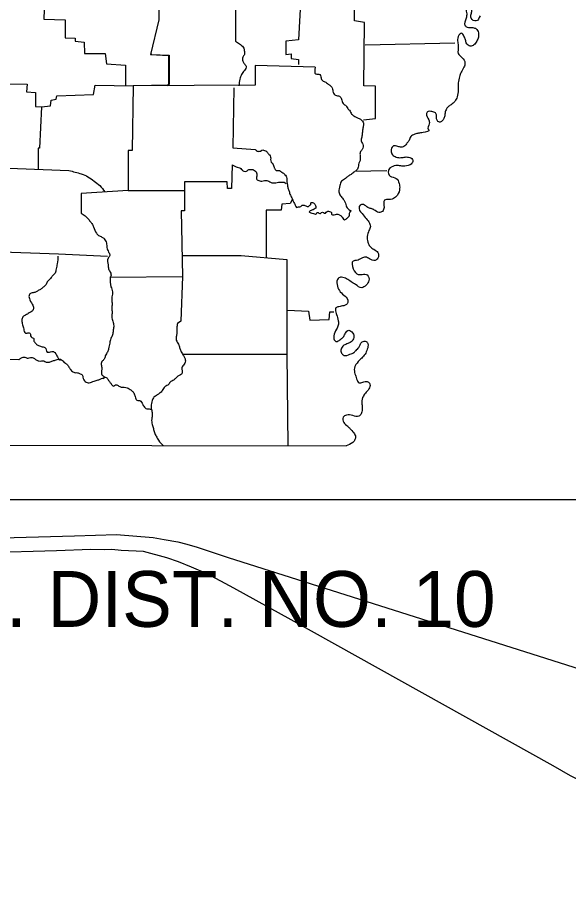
# Model space of a CAD drawing. Extents: x 1671357 to 13005564, y 567358 to 14261451.
# Drawn here: x 12758336.04 to 12758345.91, y 14259847.06 to 14259862.6 of the extents above; entities that cross this region are included whole.
import ezdxf

# ---------------------------------------------------------------- set-up
doc = ezdxf.new("R2010")
doc.units = 0
for name, color, linetype in [('1', 7, 'Continuous'), ('2', 7, 'Continuous'), ('40', 7, 'Continuous'), ('60', 7, 'Continuous')]:
    doc.layers.add(name, color=color, linetype=linetype)

msp = doc.modelspace()

# ---------------------------------------------------------------- linework, layer by layer
at = {"layer": '1'}
msp.add_line((12758342.084, 14259859.844), (12758342.654, 14259859.854), dxfattribs=at)
for points in [[(12758339.534, 14259863.784), (12758339.534, 14259863.274), (12758339.944, 14259863.264), (12758339.944, 14259862.174)], [(12758338.404, 14259863.654), (12758338.574, 14259863.644), (12758338.574, 14259862.554), (12758338.424, 14259861.934), (12758338.744, 14259861.914), (12758338.744, 14259861.394)], [(12758342.234, 14259860.764), (12758342.454, 14259860.784), (12758342.454, 14259861.364), (12758342.244, 14259861.374), (12758342.254, 14259862.504), (12758342.074, 14259862.534), (12758342.074, 14259863.294), (12758344.504, 14259863.314)], [(12758336.203, 14259862.934), (12758336.523, 14259862.914), (12758336.513, 14259862.564), (12758336.893, 14259862.554), (12758336.893, 14259862.234), (12758337.073, 14259862.224), (12758337.073, 14259862.174), (12758337.233, 14259862.154), (12758337.243, 14259861.954), (12758337.613, 14259861.954), (12758337.633, 14259861.764), (12758337.973, 14259861.744), (12758337.973, 14259861.374)], [(12758341.114, 14259862.974), (12758341.074, 14259862.194), (12758340.844, 14259862.174), (12758340.844, 14259861.934), (12758340.944, 14259861.944), (12758340.944, 14259861.864), (12758341.074, 14259861.844), (12758341.074, 14259861.754)], [(12758342.264, 14259862.104), (12758343.874, 14259862.144)], [(12758338.434, 14259861.944), (12758338.434, 14259861.934), (12758338.754, 14259861.924), (12758338.754, 14259861.394)], [(12758341.374, 14259861.704), (12758340.294, 14259861.734), (12758340.294, 14259861.384), (12758338.113, 14259861.374), (12758338.093, 14259860.214), (12758338.023, 14259860.214), (12758338.023, 14259859.494), (12758337.183, 14259859.444), (12758337.183, 14259859.093)], [(12758333.803, 14259860.934), (12758335.433, 14259860.914), (12758335.463, 14259861.184), (12758335.593, 14259861.184), (12758335.593, 14259861.414), (12758336.213, 14259861.404), (12758336.203, 14259861.264), (12758336.363, 14259861.254), (12758336.363, 14259861.004), (12758336.473, 14259860.994), (12758336.433, 14259860.254), (12758336.413, 14259860.254), (12758336.413, 14259859.874)], [(12758336.473, 14259860.994), (12758336.633, 14259861.014), (12758336.643, 14259861.114), (12758336.733, 14259861.134), (12758336.743, 14259861.194), (12758337.403, 14259861.214), (12758337.433, 14259861.384), (12758338.113, 14259861.374)], [(12758338.754, 14259861.384), (12758338.123, 14259861.374)], [(12758338.714, 14259861.374), (12758338.754, 14259861.414)], [(12758339.914, 14259861.334), (12758339.894, 14259860.264), (12758340.294, 14259860.234)], [(12758333.473, 14259860.174), (12758333.463, 14259860.334), (12758333.513, 14259860.334), (12758333.533, 14259860.704), (12758333.973, 14259860.674), (12758333.963, 14259860.454), (12758334.533, 14259860.414), (12758334.533, 14259860.284), (12758335.053, 14259860.254), (12758335.133, 14259860.094), (12758335.083, 14259860.024), (12758335.113, 14259859.924), (12758336.963, 14259859.854)], [(12758339.884, 14259859.954), (12758339.874, 14259859.534), (12758339.804, 14259859.534), (12758339.794, 14259859.654), (12758339.034, 14259859.654), (12758339.034, 14259859.133), (12758338.974, 14259859.133), (12758338.994, 14259857.953)], [(12758338.023, 14259859.494), (12758339.024, 14259859.494)], [(12758340.964, 14259859.344), (12758340.924, 14259859.263), (12758340.774, 14259859.253), (12758340.764, 14259859.143), (12758340.494, 14259859.143), (12758340.494, 14259858.293)], [(12758335.593, 14259858.403), (12758336.773, 14259858.363), (12758337.653, 14259858.323)], [(12758338.984, 14259858.333), (12758340.044, 14259858.333), (12758340.864, 14259858.263)], [(12758340.864, 14259858.263), (12758340.864, 14259856.563), (12758340.884, 14259854.923)], [(12758337.703, 14259857.943), (12758338.994, 14259857.953), (12758338.964, 14259857.153), (12758338.904, 14259857.113)], [(12758340.874, 14259857.353), (12758341.254, 14259857.333), (12758341.274, 14259857.173), (12758341.624, 14259857.183), (12758341.634, 14259857.323), (12758341.704, 14259857.323)], [(12758331.473, 14259857.243), (12758331.483, 14259854.943), (12758341.924, 14259854.923)], [(12758336.063, 14259856.463), (12758334.843, 14259856.503), (12758334.843, 14259856.793)], [(12758339.014, 14259856.563), (12758340.864, 14259856.563)]]:
    msp.add_lwpolyline(points, dxfattribs=at)
for points in [[(12758344.324, 14259862.624), (12758344.254, 14259862.534), (12758344.164, 14259862.584), (12758344.164, 14259862.654), (12758344.174, 14259862.724), (12758344.144, 14259862.774), (12758344.084, 14259862.754), (12758344.084, 14259862.664), (12758344.074, 14259862.584), (12758344.054, 14259862.454), (12758344.094, 14259862.424), (12758344.194, 14259862.414), (12758344.254, 14259862.394), (12758344.294, 14259862.324), (12758344.294, 14259862.244), (12758344.264, 14259862.174), (12758344.214, 14259862.104), (12758344.144, 14259862.084), (12758344.084, 14259862.124), (12758344.064, 14259862.194), (12758344.034, 14259862.264), (12758343.994, 14259862.314), (12758343.934, 14259862.254), (12758343.924, 14259862.154), (12758343.934, 14259862.074), (12758343.934, 14259861.954), (12758344.004, 14259861.874), (12758344.054, 14259861.784), (12758344.034, 14259861.704), (12758343.984, 14259861.614), (12758343.954, 14259861.534), (12758343.934, 14259861.424), (12758343.934, 14259861.294), (12758343.914, 14259861.174), (12758343.874, 14259861.094), (12758343.804, 14259861.034), (12758343.754, 14259860.994), (12758343.714, 14259860.944), (12758343.694, 14259860.864), (12758343.684, 14259860.804), (12758343.634, 14259860.734), (12758343.584, 14259860.724), (12758343.554, 14259860.754), (12758343.544, 14259860.804), (12758343.544, 14259860.854), (12758343.514, 14259860.894), (12758343.444, 14259860.914), (12758343.394, 14259860.914), (12758343.364, 14259860.874), (12758343.404, 14259860.764), (12758343.414, 14259860.694), (12758343.394, 14259860.594), (12758343.404, 14259860.584), (12758343.304, 14259860.534), (12758343.224, 14259860.524), (12758343.154, 14259860.504), (12758343.084, 14259860.464), (12758343.054, 14259860.394), (12758343.014, 14259860.344), (12758342.974, 14259860.294), (12758342.914, 14259860.274), (12758342.854, 14259860.284), (12758342.774, 14259860.294), (12758342.734, 14259860.234), (12758342.744, 14259860.154), (12758342.804, 14259860.104), (12758342.884, 14259860.084), (12758342.964, 14259860.094), (12758343.044, 14259860.094), (12758343.114, 14259860.054), (12758343.104, 14259859.984), (12758343.034, 14259859.944), (12758342.924, 14259859.934), (12758342.844, 14259859.944), (12758342.734, 14259859.914), (12758342.684, 14259859.854), (12758342.714, 14259859.754), (12758342.824, 14259859.714), (12758342.874, 14259859.624), (12758342.884, 14259859.534), (12758342.844, 14259859.414), (12758342.794, 14259859.364), (12758342.694, 14259859.334), (12758342.614, 14259859.323), (12758342.604, 14259859.193), (12758342.574, 14259859.123), (12758342.514, 14259859.103), (12758342.424, 14259859.153), (12758342.374, 14259859.173), (12758342.314, 14259859.193), (12758342.234, 14259859.243), (12758342.174, 14259859.233), (12758342.184, 14259859.113), (12758342.194, 14259859.103), (12758342.264, 14259859.013), (12758342.334, 14259858.933), (12758342.364, 14259858.853)], [(12758339.944, 14259862.174), (12758340.014, 14259862.124), (12758340.084, 14259862.064), (12758340.104, 14259861.984), (12758340.104, 14259861.934), (12758340.074, 14259861.884), (12758340.074, 14259861.814), (12758340.104, 14259861.764), (12758340.134, 14259861.724), (12758340.104, 14259861.644), (12758340.054, 14259861.574), (12758340.024, 14259861.494), (12758340.004, 14259861.374)], [(12758341.374, 14259861.704), (12758341.384, 14259861.584), (12758341.454, 14259861.574), (12758341.474, 14259861.534), (12758341.494, 14259861.474), (12758341.544, 14259861.444), (12758341.604, 14259861.404), (12758341.644, 14259861.374), (12758341.674, 14259861.334), (12758341.694, 14259861.254), (12758341.734, 14259861.204), (12758341.804, 14259861.184), (12758341.844, 14259861.134), (12758341.874, 14259861.054), (12758341.924, 14259861.014), (12758341.964, 14259860.954), (12758341.984, 14259860.934), (12758342.024, 14259860.864), (12758342.064, 14259860.834), (12758342.094, 14259860.814), (12758342.144, 14259860.794), (12758342.194, 14259860.764), (12758342.234, 14259860.704), (12758342.234, 14259860.664), (12758342.224, 14259860.594), (12758342.214, 14259860.524), (12758342.204, 14259860.454), (12758342.194, 14259860.384), (12758342.224, 14259860.324), (12758342.214, 14259860.234), (12758342.184, 14259860.194), (12758342.174, 14259860.134), (12758342.174, 14259860.034), (12758342.154, 14259859.984), (12758342.134, 14259859.894), (12758342.094, 14259859.844)], [(12758340.294, 14259860.234), (12758340.334, 14259860.204), (12758340.394, 14259860.204), (12758340.434, 14259860.224), (12758340.464, 14259860.214), (12758340.504, 14259860.194), (12758340.534, 14259860.154), (12758340.554, 14259860.134), (12758340.574, 14259860.094), (12758340.574, 14259860.054), (12758340.584, 14259860.004), (12758340.604, 14259859.984), (12758340.624, 14259859.944), (12758340.634, 14259859.914), (12758340.644, 14259859.894), (12758340.674, 14259859.854), (12758340.704, 14259859.854), (12758340.734, 14259859.854), (12758340.764, 14259859.834), (12758340.814, 14259859.794), (12758340.824, 14259859.784), (12758340.864, 14259859.714), (12758340.864, 14259859.664), (12758340.874, 14259859.604), (12758340.884, 14259859.544), (12758340.904, 14259859.484), (12758340.914, 14259859.444), (12758340.944, 14259859.384), (12758340.964, 14259859.344), (12758340.984, 14259859.293), (12758341.014, 14259859.233), (12758341.034, 14259859.193), (12758341.074, 14259859.203), (12758341.114, 14259859.213), (12758341.134, 14259859.233), (12758341.174, 14259859.233), (12758341.204, 14259859.223), (12758341.254, 14259859.213), (12758341.274, 14259859.233), (12758341.294, 14259859.243), (12758341.294, 14259859.273), (12758341.324, 14259859.283), (12758341.354, 14259859.263), (12758341.384, 14259859.213), (12758341.384, 14259859.193), (12758341.374, 14259859.173), (12758341.334, 14259859.153), (12758341.284, 14259859.133), (12758341.264, 14259859.113), (12758341.314, 14259859.093), (12758341.394, 14259859.083), (12758341.414, 14259859.103), (12758341.464, 14259859.083), (12758341.484, 14259859.103), (12758341.554, 14259859.093), (12758341.584, 14259859.123), (12758341.644, 14259859.113), (12758341.664, 14259859.103), (12758341.664, 14259859.073), (12758341.714, 14259859.063), (12758341.754, 14259859.073), (12758341.804, 14259859.063), (12758341.844, 14259859.033), (12758341.864, 14259859.003), (12758341.894, 14259858.973), (12758341.924, 14259858.983), (12758341.944, 14259859.003), (12758341.984, 14259859.053), (12758341.984, 14259859.083), (12758341.994, 14259859.103), (12758342.014, 14259859.133)], [(12758339.884, 14259859.954), (12758339.934, 14259859.934), (12758339.974, 14259859.914), (12758340.024, 14259859.904), (12758340.054, 14259859.874), (12758340.094, 14259859.844), (12758340.144, 14259859.844), (12758340.184, 14259859.874), (12758340.224, 14259859.874), (12758340.254, 14259859.874), (12758340.284, 14259859.854), (12758340.314, 14259859.834), (12758340.324, 14259859.794), (12758340.324, 14259859.754), (12758340.324, 14259859.694), (12758340.344, 14259859.684), (12758340.414, 14259859.664), (12758340.464, 14259859.674), (12758340.504, 14259859.674), (12758340.544, 14259859.664), (12758340.574, 14259859.644), (12758340.594, 14259859.634), (12758340.634, 14259859.634), (12758340.664, 14259859.634), (12758340.714, 14259859.644), (12758340.734, 14259859.644), (12758340.784, 14259859.644), (12758340.814, 14259859.644), (12758340.854, 14259859.624)], [(12758336.963, 14259859.854), (12758337.183, 14259859.794), (12758337.303, 14259859.744), (12758337.413, 14259859.664), (12758337.513, 14259859.584), (12758337.603, 14259859.474)], [(12758342.074, 14259859.834), (12758342.014, 14259859.784), (12758341.964, 14259859.754), (12758341.914, 14259859.714), (12758341.844, 14259859.664), (12758341.814, 14259859.584), (12758341.794, 14259859.474), (12758341.824, 14259859.404), (12758341.874, 14259859.344), (12758341.904, 14259859.293), (12758341.934, 14259859.203), (12758341.994, 14259859.143), (12758342.014, 14259859.133)], [(12758337.183, 14259859.093), (12758337.253, 14259859.043), (12758337.303, 14259858.993), (12758337.343, 14259858.943), (12758337.373, 14259858.903), (12758337.403, 14259858.843), (12758337.453, 14259858.733), (12758337.493, 14259858.693), (12758337.553, 14259858.663), (12758337.593, 14259858.633), (12758337.633, 14259858.553), (12758337.643, 14259858.473), (12758337.673, 14259858.393), (12758337.693, 14259858.333), (12758337.663, 14259858.283), (12758337.663, 14259858.163), (12758337.673, 14259858.093), (12758337.703, 14259858.033), (12758337.713, 14259857.963), (12758337.703, 14259857.943)], [(12758342.364, 14259858.853), (12758342.334, 14259858.783), (12758342.304, 14259858.673), (12758342.314, 14259858.573), (12758342.354, 14259858.493), (12758342.424, 14259858.443), (12758342.494, 14259858.383), (12758342.494, 14259858.283), (12758342.444, 14259858.243), (12758342.344, 14259858.273), (12758342.274, 14259858.303), (12758342.204, 14259858.283), (12758342.114, 14259858.243), (12758342.054, 14259858.233), (12758342.054, 14259858.093), (12758342.144, 14259857.993), (12758342.214, 14259857.993), (12758342.304, 14259857.983), (12758342.334, 14259857.883), (12758342.284, 14259857.803), (12758342.204, 14259857.753), (12758342.094, 14259857.813), (12758342.014, 14259857.863), (12758341.934, 14259857.913), (12758341.844, 14259857.943), (12758341.784, 14259857.923), (12758341.764, 14259857.813), (12758341.804, 14259857.703), (12758341.884, 14259857.623), (12758341.954, 14259857.533), (12758341.934, 14259857.453), (12758341.884, 14259857.433), (12758341.794, 14259857.413), (12758341.744, 14259857.393), (12758341.734, 14259857.363), (12758341.754, 14259857.273), (12758341.784, 14259857.163), (12758341.784, 14259857.083), (12758341.754, 14259857.013), (12758341.704, 14259856.893), (12758341.714, 14259856.823), (12758341.744, 14259856.793), (12758341.784, 14259856.803), (12758341.844, 14259856.843), (12758341.884, 14259856.883), (12758341.914, 14259856.943), (12758341.974, 14259856.993), (12758342.044, 14259856.943), (12758342.064, 14259856.863), (12758342.014, 14259856.783), (12758341.954, 14259856.753), (12758341.884, 14259856.723), (12758341.834, 14259856.653), (12758341.844, 14259856.583), (12758341.884, 14259856.543), (12758341.994, 14259856.563), (12758342.064, 14259856.593), (12758342.104, 14259856.633), (12758342.154, 14259856.683), (12758342.174, 14259856.733), (12758342.214, 14259856.783), (12758342.284, 14259856.793), (12758342.314, 14259856.753), (12758342.304, 14259856.653), (12758342.264, 14259856.563), (12758342.204, 14259856.493), (12758342.144, 14259856.433), (12758342.074, 14259856.313), (12758342.084, 14259856.213), (12758342.114, 14259856.123), (12758342.154, 14259856.053), (12758342.224, 14259856.063), (12758342.304, 14259856.073), (12758342.344, 14259856.043), (12758342.344, 14259855.963), (12758342.284, 14259855.883), (12758342.234, 14259855.813), (12758342.204, 14259855.703), (12758342.214, 14259855.633), (12758342.214, 14259855.573), (12758342.194, 14259855.493), (12758342.154, 14259855.453), (12758342.044, 14259855.463), (12758341.934, 14259855.473), (12758341.874, 14259855.433), (12758341.884, 14259855.343), (12758341.954, 14259855.273), (12758341.994, 14259855.233), (12758342.064, 14259855.153), (12758342.094, 14259855.083), (12758342.084, 14259855.033), (12758342.044, 14259854.983), (12758341.924, 14259854.923)], [(12758336.763, 14259858.323), (12758336.753, 14259858.183), (12758336.733, 14259858.093), (12758336.713, 14259858.013), (12758336.673, 14259857.973), (12758336.633, 14259857.923), (12758336.583, 14259857.873), (12758336.553, 14259857.813), (12758336.513, 14259857.773), (12758336.463, 14259857.733), (12758336.413, 14259857.703), (12758336.363, 14259857.673), (12758336.303, 14259857.663), (12758336.253, 14259857.633), (12758336.253, 14259857.563), (12758336.303, 14259857.463), (12758336.323, 14259857.423), (12758336.323, 14259857.363), (12758336.303, 14259857.333), (12758336.263, 14259857.313), (12758336.203, 14259857.273), (12758336.163, 14259857.253), (12758336.123, 14259857.203), (12758336.123, 14259857.133), (12758336.143, 14259857.053), (12758336.153, 14259857.013), (12758336.183, 14259856.943), (12758336.213, 14259856.943), (12758336.263, 14259856.943), (12758336.273, 14259856.923), (12758336.273, 14259856.913), (12758336.283, 14259856.873), (12758336.333, 14259856.843), (12758336.333, 14259856.813), (12758336.363, 14259856.763), (12758336.403, 14259856.723), (12758336.433, 14259856.713), (12758336.503, 14259856.693), (12758336.533, 14259856.683), (12758336.573, 14259856.603), (12758336.613, 14259856.603), (12758336.653, 14259856.613), (12758336.713, 14259856.593), (12758336.733, 14259856.563), (12758336.763, 14259856.503), (12758336.793, 14259856.463), (12758336.813, 14259856.463)], [(12758337.703, 14259857.943), (12758337.713, 14259857.773), (12758337.743, 14259857.683), (12758337.733, 14259857.593), (12758337.733, 14259857.503), (12758337.733, 14259857.423), (12758337.733, 14259857.353), (12758337.733, 14259857.273), (12758337.733, 14259857.213), (12758337.753, 14259857.133), (12758337.763, 14259857.053), (12758337.753, 14259856.983), (12758337.743, 14259856.913), (12758337.713, 14259856.843), (12758337.693, 14259856.763), (12758337.673, 14259856.663), (12758337.653, 14259856.603), (12758337.613, 14259856.533), (12758337.593, 14259856.473), (12758337.553, 14259856.433), (12758337.543, 14259856.363), (12758337.553, 14259856.293), (12758337.543, 14259856.243), (12758337.563, 14259856.183), (12758337.613, 14259856.153)], [(12758338.904, 14259857.113), (12758338.894, 14259857.033), (12758338.894, 14259856.943), (12758338.884, 14259856.873), (12758338.884, 14259856.813), (12758338.924, 14259856.743), (12758338.944, 14259856.683), (12758338.964, 14259856.623), (12758339.004, 14259856.553), (12758339.034, 14259856.503), (12758339.044, 14259856.423), (12758339.024, 14259856.383), (12758338.984, 14259856.323), (12758338.984, 14259856.213), (12758338.934, 14259856.183), (12758338.864, 14259856.123), (12758338.824, 14259856.093), (12758338.784, 14259856.073), (12758338.744, 14259856.023), (12758338.684, 14259855.983), (12758338.634, 14259855.913), (12758338.584, 14259855.863), (12758338.544, 14259855.833), (12758338.484, 14259855.793), (12758338.454, 14259855.733), (12758338.434, 14259855.633), (12758338.444, 14259855.553), (12758338.454, 14259855.483), (12758338.444, 14259855.403), (12758338.454, 14259855.303), (12758338.474, 14259855.233), (12758338.494, 14259855.163), (12758338.524, 14259855.093), (12758338.564, 14259855.023), (12758338.654, 14259854.923)], [(12758336.063, 14259856.463), (12758336.103, 14259856.493), (12758336.153, 14259856.513), (12758336.193, 14259856.503), (12758336.233, 14259856.493), (12758336.273, 14259856.503), (12758336.333, 14259856.493), (12758336.373, 14259856.463), (12758336.423, 14259856.443), (12758336.473, 14259856.443), (12758336.513, 14259856.443), (12758336.553, 14259856.423), (12758336.613, 14259856.423), (12758336.673, 14259856.443), (12758336.733, 14259856.463), (12758336.813, 14259856.473), (12758336.873, 14259856.423), (12758336.923, 14259856.383), (12758336.963, 14259856.333), (12758336.993, 14259856.283), (12758337.023, 14259856.253), (12758337.073, 14259856.233), (12758337.113, 14259856.233), (12758337.163, 14259856.213), (12758337.193, 14259856.203), (12758337.213, 14259856.153), (12758337.253, 14259856.073), (12758337.323, 14259856.053), (12758337.413, 14259856.083), (12758337.483, 14259856.103), (12758337.533, 14259856.123), (12758337.563, 14259856.133), (12758337.593, 14259856.133), (12758337.583, 14259856.143), (12758337.613, 14259856.153), (12758337.653, 14259856.123), (12758337.673, 14259856.093), (12758337.703, 14259856.053), (12758337.733, 14259856.013), (12758337.763, 14259855.993), (12758337.793, 14259856.013), (12758337.843, 14259856.003), (12758337.873, 14259855.983), (12758337.923, 14259855.973), (12758337.953, 14259855.973), (12758338.003, 14259855.963), (12758338.043, 14259855.943), (12758338.073, 14259855.923), (12758338.113, 14259855.883), (12758338.143, 14259855.823), (12758338.153, 14259855.783), (12758338.194, 14259855.733), (12758338.234, 14259855.733), (12758338.284, 14259855.663), (12758338.304, 14259855.633), (12758338.354, 14259855.583), (12758338.384, 14259855.583), (12758338.444, 14259855.573)]]:
    msp.add_spline(points, degree=3, dxfattribs=at)
at = {"layer": '2'}
msp.add_line((12758241.074, 14259853.963), (12758347.684, 14259853.963), dxfattribs=at)
at = {"layer": '40'}
for points in [[(12758331.126, 14259853.145), (12758331.376, 14259853.15), (12758333.818, 14259853.221), (12758337.06, 14259853.309), (12758337.813, 14259853.332)], [(12758337.813, 14259853.332), (12758338.469, 14259853.281), (12758338.666, 14259853.247), (12758338.914, 14259853.201), (12758339.073, 14259853.158)], [(12758339.073, 14259853.158), (12758339.257, 14259853.108), (12758339.811, 14259852.924), (12758350.442, 14259849.546), (12758352.661, 14259848.837), (12758353.583, 14259848.542), (12758353.813, 14259848.457), (12758354.103, 14259848.325), (12758354.264, 14259848.222), (12758354.519, 14259848.081), (12758354.666, 14259848.002), (12758354.852, 14259847.866), (12758355.022, 14259847.74), (12758355.158, 14259847.613), (12758355.711, 14259847.061)], [(12758338.3, 14259853.028), (12758337.897, 14259853.049), (12758337.897, 14259853.049), (12758337.731, 14259853.064), (12758337.591, 14259853.06), (12758337.352, 14259853.063), (12758336.741, 14259853.044), (12758334.216, 14259852.968), (12758329.547, 14259852.845), (12758328.629, 14259852.812), (12758328.365, 14259852.782), (12758327.239, 14259852.626), (12758324.244, 14259852.349)], [(12758340.942, 14259851.802), (12758339.913, 14259852.375), (12758339.438, 14259852.627), (12758339.156, 14259852.751), (12758338.926, 14259852.846), (12758338.715, 14259852.915), (12758338.3, 14259853.028)], [(12758349.335, 14259848.156), (12758348.941, 14259848.156), (12758348.657, 14259848.178), (12758348.314, 14259848.222), (12758347.774, 14259848.323), (12758347.459, 14259848.403), (12758347.199, 14259848.473), (12758346.937, 14259848.57), (12758346.669, 14259848.669), (12758346.306, 14259848.824), (12758345.946, 14259849.012), (12758345.631, 14259849.189), (12758340.942, 14259851.802)]]:
    msp.add_lwpolyline(points, dxfattribs=at)

# ---------------------------------------------------------------- texts
at = {"layer": '60'}
msp.add_text('ARK. HWY. DIST. NO. 10', height=1, dxfattribs=at).set_placement((12758329.221, 14259851.679))

doc.saveas('drawing.dxf')
